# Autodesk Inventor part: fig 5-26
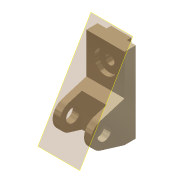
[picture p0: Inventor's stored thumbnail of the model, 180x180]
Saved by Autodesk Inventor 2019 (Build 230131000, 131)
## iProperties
Shininess: 65.0
Angle Display Precision: 2
Document Length Units: 11269
Document Angle Units: 11279
Document Time Units: 11290
Document Mass Units: 11283
Document Length Units Precision: 3
Document Angle Units Precision: 2
Compacted: False
Created: 2001-11
Part Number: fig 5-26
Document SubType Name: Modeling
Designer: Renu Muthoo
Density: 1 g/cm^3
Material: Generic
Appearance: Metal-Titanium (Polished)
Density: 0.0
Volumn: 0.0
Area: 0.0
PropertySet Name: Model Information
Control State: 0
Master: False
Checked Out: False
Author: Renu Muthoo
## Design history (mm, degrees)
node "Sketch1"
sketch "Sketch2"
  geometry: L1 (33.257, 104.664)-(33.257, -75.336); L2 (33.257, -75.336)-(8.257, -75.336); L3 (8.257, -75.336)-(-45.451, -59.045); L4 (-45.451, -1.628)-(8.257, 14.664); L5 (8.257, 14.664)-(8.257, 104.664); L6 (8.257, 104.664)-(33.257, 104.664); C1 r 15 at (-36.743, -30.336); A1 r 30 centre (-36.743, -30.336) between (-45.451, -1.628) and (-45.451, -59.045)
  constraints: 12 end point, 2 centre point, 2 equal length, 2 parallel, 2 point on circle, 2 tangent, 1 coincident, 1 perpendicular, 1 vertical
  dimensions: "d0" = 180 distance of L1.start L1.end; "d1" = 30 radius of A1; "d2" = 25 distance of L5.end L1.start; "d3" = 45 distance from line of L2 A1.centre; "d4" = 70 distance from line of L1 A1.centre; "d5" = 30 diameter of C1
extrude "Extrusion1" new body sketch "Sketch2" distance "d6" = 85; taper "d7" = 0 deg
workplane "Work Plane1"
sketch "Sketch3"
  geometry: L1 (15, 62.364)-(70, 62.364); L2 (70, 62.364)-(70, -52.386); L3 (70, -52.386)-(15, -52.386); L4 (15, -52.386)-(15, 62.364); L5 (0, -45)-(0, -28.708) reference
  constraints: 8 end point, 2 parallel, 1 horizontal, 1 perpendicular
  dimensions: "d8" = 55 distance of L1.start L1.end; "d9" = 15 distance between parallel lines of L5 L4
extrude "Extrusion2" cut sketch "Sketch3" distance "d10" = 50; taper "d11" = 0 deg
sketch "Sketch4"
  geometry: L1 (0, 25)-(85, 25) reference; L2 (0, 0)-(0, 25) reference; L3 (20, 25)-(65, 25); L4 (65, 25)-(65, 35); L5 (65, 35)-(20, 35); L6 (20, 35)-(20, 25)
  constraints: 8 end point, 2 parallel, 1 horizontal, 1 perpendicular, 1 point on line
  dimensions: "d12" = 45 distance of L4.end L5.end; "d13" = 10 distance of L3.end L4.end; "d14" = 20 distance between parallel lines of L2 L6
extrude "Extrusion3" join sketch "Sketch4" stored distance "d15" = 50; taper "d16" = 0 deg
sketch "Sketch5"
  geometry: L1 (85, 0)-(85, 90) reference; L2 (0, 90)-(85, 90) reference; 1 further point
  dimensions: "d17" = 42 distance from line of L2 point (42.5, 48); "d18" = 42.5 distance from line of L1 point (42.5, 48)
hole "Hole1" sketch "Sketch5" at (42.5, 48) diameter "d19" = 20; stored, may be unused: countersink angle "d23" = 82 deg, drill point angle "d25" = 118 deg; dims "d20" = 6, "d21" = 50, "d22" = 10, "d24" = 8
workplane "Work Plane12"
body "Solid1"
